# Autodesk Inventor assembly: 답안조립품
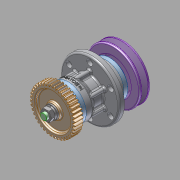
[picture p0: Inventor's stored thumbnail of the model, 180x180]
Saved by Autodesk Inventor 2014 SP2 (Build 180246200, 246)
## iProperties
Created: 2024-04
Part Number: 답안조립품
Document SubType Name: Assembly
Designer: Administrator
Author: Administrator
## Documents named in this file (14)
- C:\Users\Administrator\Desktop\740404V1009\답안조립품.iam
- C:\Users\Administrator\Desktop\740404V1009\본체.ipt
- C:\Users\Administrator\Desktop\740404V1009\가져온 구성요소\축\축.ipt
- C:\Users\Administrator\Desktop\740404V1009\가져온 구성요소\깊은 홈 볼 베어링 6204\깊은 홈 볼 베어링 6204.ipt
- C:\Users\Administrator\Desktop\740404V1009\가져온 구성요소\커버\커버.ipt
- C:\Users\Administrator\Desktop\740404V1009\가져온 구성요소\육각 소켓 머리 볼트 M4x10\육각 소켓 머리 볼트 M4x10.ipt
- C:\Users\Administrator\Desktop\740404V1009\가져온 구성요소\오일 실 20 32 5\오일 실 20 32 5.ipt
- C:\Users\Administrator\Desktop\740404V1009\가져온 구성요소\평행키 4x4x12\평행키 4x4x12.ipt
- C:\Users\Administrator\Desktop\740404V1009\가져온 구성요소\평행키 4x4x18\평행키 4x4x18.ipt
- C:\Users\Administrator\Desktop\740404V1009\가져온 구성요소\스퍼기어\스퍼기어.ipt
- C:\Users\Administrator\Desktop\740404V1009\가져온 구성요소\V-벨트풀리\V-벨트풀리.ipt
- C:\Users\Administrator\Desktop\740404V1009\가져온 구성요소\평와셔 M12\평와셔 M12.ipt
- C:\Users\Administrator\Desktop\740404V1009\가져온 구성요소\스프링와셔 M12\스프링와셔 M12.ipt
- C:\Users\Administrator\Desktop\740404V1009\가져온 구성요소\육각너트 M12x1\육각너트 M12x1.ipt
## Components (1 placed, 1 different names)
1. V-벨트풀리:1
